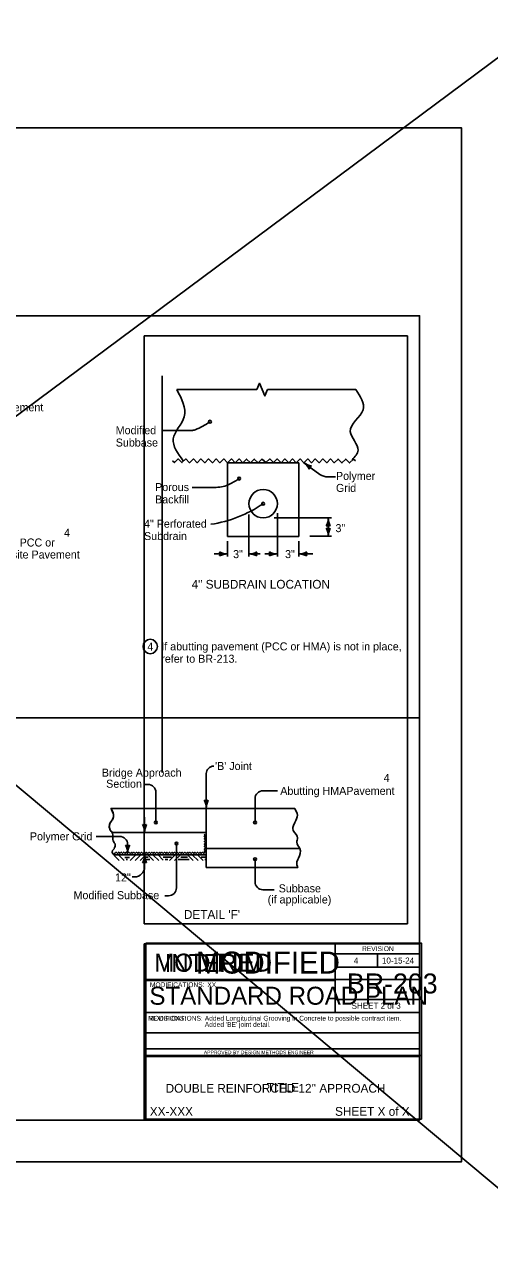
# Model space of a CAD drawing. Extents: x 8925 to 81668, y 4369 to 11918.
# Drawn here: x 15851 to 17013, y 4408 to 7462 of the extents above; entities that cross this region are included whole.
import ezdxf

# ---------------------------------------------------------------- set-up
doc = ezdxf.new("R2010")
doc.units = 0
for name, color, linetype in [('dsnCellElements', 7, 'Continuous'), ('dsnNonPlotable', 7, 'Continuous'), ('dsnShtPlotShapeBatchPrint', 7, 'Continuous'), ('dsnStdBlock', 7, 'Continuous'), ('dsnstdblockInterim', 7, 'Continuous'), ('dsnStdBlockModified', 7, 'Continuous'), ('dsnStdBlockNotModified', 7, 'Continuous'), ('dsnStdBorder', 7, 'Continuous'), ('dsnStdLabel', 7, 'Continuous'), ('dsnstdModifiedBlock', 7, 'Continuous'), ('Level 1', 7, 'Continuous'), ('Level 3', 7, 'Continuous'), ('Level 5', 7, 'Continuous'), ('SheetBorder', 7, 'Continuous')]:
    doc.layers.add(name, color=color, linetype=linetype)

msp = doc.modelspace()

# ---------------------------------------------------------------- linework, layer by layer
at = {"layer": 'dsnNonPlotable'}
msp.add_line((13703, 5728.9), (16838, 5728.9), dxfattribs=at)
at = {"layer": 'dsnShtPlotShapeBatchPrint'}
for p, q in [((16588.9, 6336.9), (16549, 6366.6)), ((16609.5, 6331.1), (16627.8, 6331.1)), ((16411.5, 6236.7), (16411.5, 6131.9)), ((16482.8, 6240.1), (16482.8, 6131.9)), ((16474.5, 6228.5), (16618, 6228.5)), ((16609.8, 6228.5), (16609.8, 6182.9)), ((16358, 6170.6), (16358, 6131.9)), ((16536.2, 6170.6), (16536.2, 6131.9)), ((16563.6, 6182.9), (16618, 6182.9)), ((16324.7, 6138.5), (16358, 6138.5)), ((16411.5, 6138.5), (16439.4, 6138.5)), ((16451.7, 6138.5), (16482.8, 6138.5)), ((16536.2, 6138.5), (16571.4, 6138.5))]:
    msp.add_line(p, q, dxfattribs=at)
msp.add_arc((16609.5, 6370.7), 39.6, 238.7046, 270, dxfattribs=at)
at = {"layer": 'dsnStdBlock'}
msp.add_lwpolyline([(13703, 6733.9), (16838, 6733.9), (16838, 4723.9), (13703, 4723.9)], close=True, dxfattribs=at)
at = {"layer": 'dsnStdBlockModified'}
for p, q in [((16150, 6683.9), (16150, 5213.9)), ((16808, 6683.9), (16150, 6683.9)), ((16808, 6683.9), (16808, 5213.9)), ((16195, 6583.9), (16195, 5592.4)), ((16808, 5213.9), (16150, 5213.9))]:
    msp.add_line(p, q, dxfattribs=at)
at = {"layer": 'dsnStdBlockNotModified'}
msp.add_lwpolyline([(13598.5, 4619.4), (16942.5, 4619.4), (16942.5, 7203.4), (13598.5, 7203.4)], close=True, dxfattribs=at)
at = {"layer": 'dsnStdBorder'}
for p, q in [((16267.8, 6447.1), (16196.5, 6447.1)), ((16358, 6182.5), (16358, 6365.9)), ((16358, 6365.9), (16536.2, 6365.9)), ((16369.8, 6365.9), (16536.2, 6365.9)), ((16536.2, 6182.5), (16536.2, 6365.9)), ((16329.9, 6304.9), (16269.4, 6304.9)), ((16358, 6182.5), (16536.2, 6182.5)), ((16305, 5502.8), (16305, 5589.6)), ((16148.6, 5562.5), (16159.3, 5562.5)), ((16179.1, 5467.6), (16179.1, 5542.7)), ((16483, 5546.7), (16446.6, 5546.7)), ((16305, 5502.2), (16066.9, 5502.2)), ((16305, 5502.2), (16067.3, 5502.2)), ((16305, 5442.2), (16305, 5502.2)), ((16305, 5502.2), (16525.9, 5502.2)), ((16305, 5502.2), (16305, 5442.2)), ((16426.8, 5526.9), (16426.8, 5467.6)), ((16150.9, 5480.6), (16150.9, 5442.2)), ((16070, 5442.2), (16305, 5442.2)), ((16305, 5442.2), (16070, 5442.2)), ((16305, 5402.2), (16305, 5442.2)), ((16030.3, 5432.7), (16088.8, 5432.7)), ((16108.6, 5412.9), (16108.6, 5390.6)), ((16230.6, 5304.1), (16230.6, 5414.7)), ((16073.7, 5386.1), (16087.7, 5372.1)), ((16304.5, 5386.4), (16077, 5386.4)), ((16086, 5386.4), (16100, 5372.4)), ((16113.5, 5380.2), (16101.6, 5380.2)), ((16105.1, 5375.2), (16108.3, 5375.2)), ((16206, 5386.4), (16107.4, 5386.4)), ((16128.8, 5386.4), (16114.8, 5372.4)), ((16141.1, 5386.1), (16127.1, 5372.1)), ((16154, 5386.4), (16140, 5372.4)), ((16163.7, 5375.1), (16149.7, 5375.1)), ((16150.9, 5386.6), (16150.9, 5356.5)), ((16159.9, 5380.9), (16153.5, 5380.9)), ((16159.4, 5386.4), (16173.4, 5372.4)), ((16172.3, 5386.1), (16186.3, 5372.1)), ((16184.6, 5386.4), (16197.4, 5373.5)), ((16217.9, 5381), (16197.7, 5381)), ((16202.7, 5375.2), (16206, 5375.2)), ((16304.5, 5386.4), (16206, 5386.4)), ((16209.2, 5375.2), (16206, 5375.2)), ((16227.4, 5386.4), (16213.4, 5372.4)), ((16239.7, 5386.1), (16225.7, 5372.1)), ((16262.3, 5375.1), (16234.5, 5375.1)), ((16258.5, 5380.9), (16241.3, 5380.9)), ((16258.5, 5380.9), (16253.6, 5380.9)), ((16257.9, 5386.4), (16271.9, 5372.4)), ((16270.8, 5386.1), (16284.8, 5372.1)), ((16283.1, 5386.4), (16297.1, 5372.4)), ((16292.6, 5381), (16304.5, 5381)), ((16301.3, 5375.2), (16304.5, 5375.2)), ((16305, 5402.2), (16538.8, 5402.2)), ((16305, 5402.2), (16305, 5355)), ((16426.8, 5319.1), (16426.8, 5375.6)), ((16305, 5355), (16533.8, 5355)), ((16120.2, 5331.5), (16125.9, 5331.5)), ((16201.7, 5284.3), (16210.8, 5284.3)), ((16474.6, 5299.3), (16446.6, 5299.3))]:
    msp.add_line(p, q, dxfattribs=at)
for points in [[(16231.3, 6549.3), (16431.1, 6549.3), (16437.8, 6565.2), (16444.6, 6549.3)], [(16678.3, 6549.3), (16458.2, 6549.3), (16451.4, 6533.5), (16444.6, 6549.3)], [(16220.5, 6371.5), (16225.3, 6366.7), (16234.8, 6376.2), (16244.3, 6366.7), (16253.8, 6376.2), (16263.3, 6366.6), (16272.8, 6376.1), (16282.3, 6366.6), (16291.8, 6376), (16301.3, 6366.5), (16310.9, 6376), (16320.3, 6366.5), (16329.9, 6375.9), (16339.3, 6366.4), (16348.9, 6375.9), (16358.4, 6366.4), (16367.9, 6375.8), (16377.3, 6366.3), (16386.9, 6375.8), (16396.3, 6366.3), (16405.9, 6375.7), (16415.4, 6366.2), (16424.9, 6375.7), (16434.4, 6366.2), (16443.9, 6375.7), (16449.7, 6371.1)], [(16449.1, 6371.5), (16453.8, 6366.7), (16463.4, 6376.2), (16472.9, 6366.7), (16482.4, 6376.2), (16491.9, 6366.6), (16501.4, 6376.1), (16510.9, 6366.6), (16520.4, 6376), (16529.9, 6366.5), (16539.4, 6376), (16548.9, 6366.5), (16558.4, 6375.9), (16567.9, 6366.4), (16577.4, 6375.9), (16586.9, 6366.4), (16596.4, 6375.8), (16605.9, 6366.3), (16615.4, 6375.8), (16624.9, 6366.3), (16634.5, 6375.7), (16643.9, 6366.2), (16653.5, 6375.7), (16662.9, 6366.2), (16672.5, 6375.7), (16677.7, 6371.5)], [(16302.2, 5435.6), (16299.6, 5438.2)], [(16301.7, 5392.8), (16299.8, 5394.7), (16303, 5397.8), (16299.9, 5401), (16303, 5404.2), (16299.9, 5407.3), (16303.1, 5410.5), (16299.9, 5413.7), (16303.1, 5416.8), (16299.9, 5420), (16303.1, 5423.2), (16299.9, 5426.4), (16303.1, 5429.5), (16299.9, 5432.7), (16302.2, 5435.6)], [(16075.2, 5391.8), (16076.7, 5390.2), (16079.9, 5393.3), (16083.1, 5390.2), (16086.3, 5393.3), (16089.4, 5390.1), (16092.6, 5393.3), (16095.7, 5390.1), (16098.9, 5393.3), (16102.1, 5390.1), (16105.3, 5393.3), (16108.4, 5390.1), (16111.6, 5393.2), (16114.8, 5390.1), (16117.9, 5393.2), (16121.1, 5390.1), (16124.3, 5393.2), (16127.4, 5390), (16130.6, 5393.2), (16133.8, 5390), (16136.9, 5393.2), (16140.1, 5390), (16143.3, 5393.2), (16146.4, 5390), (16149.6, 5393.1), (16151, 5392)], [(16151.4, 5391.6), (16153, 5390), (16156.1, 5393.2), (16159.3, 5390), (16162.5, 5393.2), (16165.6, 5390), (16168.8, 5393.2), (16172, 5390), (16175.1, 5393.1), (16178.3, 5390), (16181.5, 5393.1), (16184.6, 5390), (16187.8, 5393.1), (16191, 5389.9), (16194.2, 5393.1), (16197.3, 5389.9), (16200.5, 5393.1), (16203.6, 5389.9), (16206.8, 5393.1), (16210, 5389.9), (16213.2, 5393), (16216.3, 5389.9), (16219.5, 5393), (16222.7, 5389.8), (16225.8, 5393), (16227.3, 5391.9)], [(16227.6, 5391.6), (16229.2, 5390), (16232.4, 5393.2), (16235.6, 5390), (16238.7, 5393.1), (16241.9, 5390), (16245.1, 5393.1), (16248.2, 5390), (16251.4, 5393.1), (16254.6, 5389.9), (16257.7, 5393.1), (16260.9, 5389.9), (16264.1, 5393.1), (16267.2, 5389.9), (16270.4, 5393.1), (16273.6, 5389.9), (16276.7, 5393), (16279.9, 5389.9), (16283.1, 5393), (16286.2, 5389.9), (16289.4, 5393), (16292.6, 5389.8), (16295.8, 5393), (16298.9, 5389.8), (16301.8, 5392.7)]]:
    msp.add_lwpolyline(points, dxfattribs=at)
for centre, radius in [((16447.1, 6264.1), 35.6), ((16165, 5907.2), 18)]:
    msp.add_circle(centre, radius, dxfattribs=at)
for centre, radius, start, end in [((16267.8, 6472.1), 25, 270, 292.4048), ((16200.8, 6634.7), 200.9, 292.4048, 304.4007), ((16273.6, 6492.6), 200.9, 296.5518, 304.4007), ((16329.9, 6379.9), 75, 270, 296.5518), ((16269.5, 6523.5), 314.4, 278.602, 304.4007), ((16567.3, 6228.5), 42.5, 331.9275, 360), ((16609.8, 6192.8), 16.4, 72.2666, 107.7334), ((16609.8, 6218.5), 16.4, 252.2666, 287.7333), ((16567.3, 6182.9), 42.5, 360, 28.0725), ((16652.3, 6228.5), 42.5, 180, 208.0725), ((16652.3, 6182.9), 42.5, 151.9275, 180), ((16322.4, 6138.5), 16.4, 342.2666, 17.7333), ((16358, 6181), 42.5, 241.9275, 270), ((16358, 6096), 42.5, 90, 118.0725), ((16411.5, 6181), 42.5, 270, 298.0725), ((16411.5, 6181), 42.5, 270, 298.0725), ((16411.5, 6096), 42.5, 61.9275, 90), ((16411.5, 6096), 42.5, 61.9275, 90), ((16447.1, 6138.5), 16.4, 162.2666, 197.7334), ((16447.1, 6138.5), 16.4, 162.2666, 197.7334), ((16447.1, 6138.5), 16.4, 342.2666, 17.7333), ((16482.8, 6181), 42.5, 241.9275, 270), ((16447.1, 6138.5), 16.4, 342.2666, 17.7333), ((16482.8, 6181), 42.5, 241.9275, 270), ((16482.8, 6096), 42.5, 90, 118.0725), ((16482.8, 6096), 42.5, 90, 118.0725), ((16536.2, 6181), 42.5, 270, 298.0725), ((16536.2, 6096), 42.5, 61.9275, 90), ((16571.8, 6138.5), 16.4, 162.2666, 197.7334), ((16323.5, 5589.6), 18.6, 90, 180), ((16159.3, 5542.7), 19.8, 0, 90), ((16446.6, 5526.9), 19.8, 90, 180), ((16305, 5538.6), 16.5, 252.2666, 287.7333), ((16262.2, 5502.8), 42.7, 360, 28.0725), ((16305, 5538.6), 16.5, 252.2666, 287.7333), ((16262.2, 5502.8), 42.7, 360, 28.0725), ((16347.7, 5502.8), 42.7, 151.9275, 180), ((16347.7, 5502.8), 42.7, 151.9275, 180), ((16150.9, 5478.1), 16.5, 252.2666, 287.7333), ((16108.1, 5442.2), 42.7, 360, 28.0725), ((16193.6, 5442.2), 42.7, 151.9275, 180), ((16088.8, 5412.9), 19.8, 0, 90), ((16108.6, 5426.5), 16.5, 252.2667, 287.7334), ((16065.9, 5390.6), 42.7, 0, 28.0725), ((16151.4, 5390.6), 42.7, 151.9275, 180), ((16108.1, 5386.6), 42.7, 331.9275, 360), ((16193.6, 5386.6), 42.7, 180, 208.0725), ((16125.9, 5356.5), 25, 270, 0), ((16150.9, 5350.8), 16.5, 72.2666, 107.7334), ((16446.6, 5319.1), 19.8, 180, 270), ((16210.8, 5304.1), 19.8, 270, 360)]:
    msp.add_arc(centre, radius, start, end, dxfattribs=at)
for points in [[(16231.3, 6549.3), (16249.8, 6481.5), (16222.6, 6425.9), (16247.3, 6371.5)], [(16678.3, 6549.3), (16696.8, 6498.8), (16664.7, 6444.4), (16684.4, 6397.5), (16669.6, 6374)], [(16066.9, 5503), (16073, 5487.8), (16072.9, 5480.8), (16063.1, 5461.5), (16064.5, 5450.2), (16071, 5440.1), (16071.6, 5424.7), (16077, 5413.8)], [(16525.9, 5502.2), (16532.5, 5485.9), (16526.4, 5467.6), (16521.8, 5457.7), (16523.3, 5445.6), (16533.2, 5428.8), (16530.9, 5418.2), (16538.8, 5402.2), (16535.5, 5377.9), (16530.9, 5367.2), (16533.8, 5354.9)], [(16077, 5413.8), (16077, 5407.3), (16070.5, 5397.1)], [(16070.5, 5397.1), (16070.5, 5390.6), (16077, 5386.4)]]:
    msp.add_spline(points, degree=3, dxfattribs=at)
msp.add_open_spline([(16067.3, 5502.2), (16069.2, 5497.4), (16071.1, 5492.6), (16073, 5487.8), (16073.9, 5485.6), (16073.3, 5483), (16072.9, 5480.8), (16071.5, 5473.9), (16064.2, 5468.3), (16063.1, 5461.5), (16062.5, 5458), (16063.2, 5453.8), (16064.5, 5450.2), (16065.6, 5447.2), (16068.4, 5444.9), (16070, 5442.2)], degree=3, dxfattribs=at)
at = {"layer": 'dsnstdModifiedBlock'}
for p, q in [((16154.3, 5074.8), (16842.3, 5074.8)), ((16154.3, 4884.8), (16842.3, 4884.8))]:
    msp.add_line(p, q, dxfattribs=at)
msp.add_lwpolyline([(16154.3, 5166.2), (16842.3, 5166.2), (16842.3, 4726.2), (16154.3, 4726.2)], close=True, dxfattribs=at)
at = {"layer": 'Level 1'}
for p, q in [((16627.1, 5163.9), (16627.1, 5072.6)), ((16627.1, 5139), (16838, 5139)), ((16732.6, 5139), (16732.6, 5105.8)), ((16627.1, 5105.8), (16838, 5105.8)), ((16150, 5072.6), (16627.1, 5072.6)), ((16627.1, 5072.6), (16627.1, 4992.6)), ((16838, 5024.8), (16627.1, 5024.8)), ((16150, 4992.6), (16838, 4992.6)), ((16150, 4941.6), (16838, 4941.6)), ((16150, 4901.6), (16838, 4901.6)), ((16150, 4882.6), (16838, 4882.6))]:
    msp.add_line(p, q, dxfattribs=at)
msp.add_lwpolyline([(16150, 5163.9), (16838, 5163.9), (16838, 4723.9), (16150, 4723.9)], close=True, dxfattribs=at)
msp.add_lwpolyline([(16150, 5163.9), (16838, 5163.9), (16838, 4723.9), (16150, 4723.9)], close=True, dxfattribs=at)
at = {"layer": 'Level 3'}
for centre, radius, start, end in [((16523.6, 6332.6), 42.5, 25.1788, 53.2513), ((16574.5, 6400.7), 42.5, 233.2513, 261.3238), ((16577.6, 6345.3), 16.4, 125.5179, 160.9846)]:
    msp.add_arc(centre, radius, start, end, dxfattribs=at)
at = {"layer": 'Level 5'}
for centre in [(16314.3, 6468.9), (16387.1, 6326.8), (16447.1, 6264.1), (16179.1, 5467.6), (16426.8, 5467.6), (16230.6, 5414.7), (16426.8, 5375.6)]:
    msp.add_circle(centre, 3.54, dxfattribs=at)
at = {"layer": 'SheetBorder'}
for p, q in [((13555.2, 7461.7), (17208.8, 4407.7)), ((17092.5, 7422.9), (13574.6, 4805.2))]:
    msp.add_line(p, q, dxfattribs=at)

# ---------------------------------------------------------------- texts
at = {"layer": 'dsnCellElements'}
for s, height, p in [('MODIFIED', 45, (16175.1, 5094.7)), ('MODIFICATIONS:', 12, (16160, 4972.2))]:
    msp.add_text(s, height=height, dxfattribs=at).set_placement(p)
at = {"layer": 'dsnNonPlotable'}
msp.add_text('REVISIONS:', height=12, dxfattribs=at).set_placement((16160, 4972.2))
at = {"layer": 'dsnShtPlotShapeBatchPrint'}
for s, p in [('Composite Pavement', (15642.2, 6495.1)), ('Modified', (16078.8, 6437.7)), ('Subbase', (16078.8, 6406.9)), ('Polymer ', (16629, 6323.5)), ('Porous', (16177.1, 6295.6)), ('Grid', (16629, 6293.5)), ('Backfill', (16177.1, 6264.8)), ('4', (15949.6, 6181.5)), ('4" Perforated ', (16149.5, 6204.1)), ('3"', (16627.8, 6193)), ('Abutting PCC or', (15733.2, 6157.1)), ('Subdrain', (16149.5, 6173.3)), ('Composite Pavement', (15733.2, 6127.1)), ('3"', (16372, 6128.1)), ('3"', (16501.8, 6128.1)), ("'B' Joint", (16327, 5598.6)), ('Bridge Approach', (16044.1, 5582)), ('4', (16748.2, 5569)), ('Section', (16055, 5554.3)), ('Abutting HMAPavement', (16489.9, 5536.5)), ('Polymer Grid', (15864.4, 5422.9)), ('12"', (16077.1, 5320)), ('Subbase', (16485.9, 5292.9)), ('Modified Subbase', (15973.4, 5275.8)), ('(if applicable)', (16458.4, 5265.1))]:
    msp.add_text(s, height=20, dxfattribs=at).set_placement(p)
at = {"layer": 'dsnstdblockInterim'}
msp.add_text('INTERIM', height=45, dxfattribs=at).set_placement((16201, 5093.6))
at = {"layer": 'dsnStdBorder'}
for s, height, p in [('4" SUBDRAIN LOCATION', 22, (16268.5, 6051.7)), ('4', 20, (16157.8, 5897.2)), ("DETAIL 'F'", 22, (16249.1, 5226.6))]:
    msp.add_text(s, height=height, dxfattribs=at).set_placement(p)
at = {"layer": 'dsnStdLabel'}
for s, p in [('If abutting pavement (PCC or HMA) is not in place, ', (16192.6, 5897.5)), ('refer to BR-213.', (16192.6, 5866.7))]:
    msp.add_text(s, height=20, dxfattribs=at).set_placement(p)
at = {"layer": 'dsnstdModifiedBlock'}
for s, height, p in [('MODIFIED', 55, (16279.4, 5089.9)), ('MODIFICATIONS:', 12, (16164.3, 5056)), ('XX', 12, (16307.6, 5056)), ('TITLE', 22, (16456.4, 4794.5)), ('XX-XXX', 22, (16163.9, 4734.5)), ('SHEET X of X', 22, (16626.7, 4734.5))]:
    msp.add_text(s, height=height, dxfattribs=at).set_placement(p)
at = {"layer": 'Level 1'}
for s, height, p in [('REVISION', 12, (16694.1, 5146.1)), ('4', 15, (16673.4, 5114.5)), ('10-15-24', 15, (16743.9, 5115)), ('BR-203', 50, (16656.3, 5040.1)), ('STANDARD ROAD PLAN', 45.001, (16163, 5012)), ('SHEET 2 of 3', 15, (16668.1, 5001.9)), ('Added Longitudinal Grooving in Concrete to possible contract item. ', 12, (16301.3, 4972.3)), ("Added 'BE' joint detail.", 12, (16301.3, 4956.8)), ('APPROVED BY DESIGN METHODS ENGINEER', 9.003, (16299, 4888.4)), ("DOUBLE REINFORCED 12'' APPROACH", 22, (16203.5, 4792.2))]:
    msp.add_text(s, height=height, dxfattribs=at).set_placement(p)

doc.saveas('drawing.dxf')
